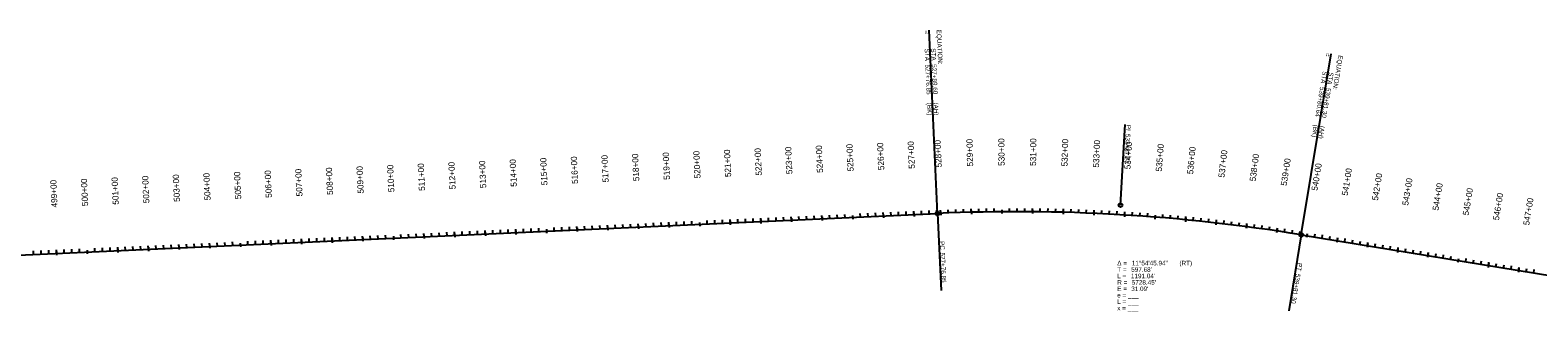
# Model space of a CAD drawing. Extents: x 22693007 to 22771804, y 6223023 to 6251673.
# Drawn here: x 22727487 to 22732405, y 6235764 to 6236738 of the extents above; entities that cross this region are included whole.
import ezdxf

# ---------------------------------------------------------------- set-up
doc = ezdxf.new("R2010")
doc.units = 0
for name, color, linetype in [('Default', 7, 'Continuous'), ('Draft_2', 7, 'Continuous'), ('NamedBoundary', 7, 'Continuous'), ('SheetBorder', 7, 'Continuous'), ('TextAlignment', 7, 'Continuous')]:
    doc.layers.add(name, color=color, linetype=linetype)

msp = doc.modelspace()

# ---------------------------------------------------------------- linework, layer by layer
at = {"layer": 'Default'}
for p, q in [((22723196, 6235810.3), (22730446.9, 6236138.4)), ((22731633.7, 6236068.7), (22733486.8, 6235764.5))]:
    msp.add_line(p, q, dxfattribs=at)
msp.add_arc((22730705.8, 6230415.9), 5728.5, 80.6784, 92.5911, dxfattribs=at)
at = {"layer": 'Draft_2'}
for p, q in [((22729870.6, 6236112.4), (22729870.1, 6236123.3)), ((22729970.5, 6236116.9), (22729970, 6236127.8)), ((22730070.4, 6236121.4), (22730069.9, 6236132.3)), ((22730170, 6236132), (22730170.6, 6236119.8)), ((22730270.2, 6236130.5), (22730269.7, 6236141.4)), ((22730370.1, 6236135), (22730369.6, 6236145.9)), ((22730457.3, 6236138.9), (22730456.8, 6236149.8)), ((22730557.2, 6236142.4), (22730556.9, 6236153.3)), ((22730657.1, 6236150.2), (22730657.2, 6236138)), ((22730757.2, 6236144.1), (22730757.3, 6236155)), ((22730857.2, 6236142.3), (22730857.5, 6236153.2)), ((22730957.1, 6236138.8), (22730957.6, 6236149.7)), ((22731057, 6236133.5), (22731057.6, 6236144.4)), ((22731157.2, 6236132.6), (22731156.2, 6236120.4)), ((22731256.3, 6236117.8), (22731257.4, 6236128.7)), ((22728771.7, 6236062.6), (22728771.2, 6236073.6)), ((22728871.6, 6236067.2), (22728871.1, 6236078.1)), ((22728971.5, 6236071.7), (22728971, 6236082.6)), ((22729071.4, 6236076.2), (22729070.9, 6236087.1)), ((22729171, 6236086.8), (22729171.6, 6236074.6)), ((22729271.2, 6236085.2), (22729270.7, 6236096.2)), ((22729371.1, 6236089.8), (22729370.6, 6236100.7)), ((22729471, 6236094.3), (22729470.5, 6236105.2)), ((22729570.9, 6236098.8), (22729570.4, 6236109.7)), ((22729670.5, 6236109.4), (22729671.1, 6236097.2)), ((22729770.7, 6236107.9), (22729770.2, 6236118.8)), ((22731355.8, 6236107.3), (22731357, 6236118.2)), ((22731455, 6236095.1), (22731456.5, 6236105.9)), ((22731554, 6236081.2), (22731555.7, 6236092)), ((22731653.2, 6236071.7), (22731651.2, 6236059.6)), ((22727772.8, 6236017.4), (22727772.3, 6236028.3)), ((22727872.7, 6236022), (22727872.2, 6236032.9)), ((22727972.6, 6236026.5), (22727972.1, 6236037.4)), ((22728072.4, 6236031), (22728072, 6236041.9)), ((22728172.1, 6236041.6), (22728172.6, 6236029.4)), ((22728272.2, 6236040), (22728271.7, 6236050.9)), ((22728372.1, 6236044.6), (22728371.6, 6236055.5)), ((22728472, 6236049.1), (22728471.5, 6236060)), ((22728571.9, 6236053.6), (22728571.4, 6236064.5)), ((22728671.6, 6236064.2), (22728672.1, 6236052)), ((22731750.8, 6236049.4), (22731752.6, 6236060.2)), ((22731849.5, 6236033.2), (22731851.3, 6236044)), ((22731948.2, 6236017), (22731950, 6236027.8)), ((22727573, 6236008.4), (22727572.5, 6236019.3)), ((22727672.6, 6236019), (22727673.1, 6236006.8)), ((22732046.9, 6236000.8), (22732048.7, 6236011.6)), ((22732146.6, 6235990.7), (22732144.6, 6235978.6)), ((22732244.2, 6235968.4), (22732246, 6235979.2)), ((22732342.9, 6235952.2), (22732344.7, 6235963))]:
    msp.add_line(p, q, dxfattribs=at)
at = {"layer": 'NamedBoundary'}
for p, q in [((22723196, 6235810.3), (22730446.9, 6236138.4)), ((22731633.7, 6236068.7), (22733486.8, 6235764.5))]:
    msp.add_line(p, q, dxfattribs=at)
msp.add_arc((22730705.8, 6230415.9), 5728.5, 80.6784, 92.5911, dxfattribs=at)
at = {"layer": 'SheetBorder'}
for p, q in [((22729795.7, 6236109), (22729795.2, 6236119.9)), ((22729820.7, 6236110.1), (22729820.2, 6236121)), ((22729845.6, 6236111.2), (22729845.1, 6236122.1)), ((22729895.6, 6236113.5), (22729895.1, 6236124.4)), ((22729920.6, 6236114.6), (22729920.1, 6236125.5)), ((22729945.5, 6236115.8), (22729945, 6236126.7)), ((22729970.2, 6236123), (22729970.8, 6236110.8)), ((22729995.5, 6236118), (22729995, 6236128.9)), ((22730020.5, 6236119.2), (22730020, 6236130.1)), ((22730045.4, 6236120.3), (22730044.9, 6236131.2)), ((22730070.1, 6236127.5), (22730070.7, 6236115.3)), ((22730095.4, 6236122.5), (22730094.9, 6236133.5)), ((22730120.4, 6236123.7), (22730119.9, 6236134.6)), ((22730145.3, 6236124.8), (22730144.8, 6236135.7)), ((22730170, 6236132), (22730170.6, 6236119.8)), ((22730195.3, 6236127.1), (22730194.8, 6236138)), ((22730220.2, 6236128.2), (22730219.8, 6236139.1)), ((22730245.2, 6236129.3), (22730244.7, 6236140.2)), ((22730269.9, 6236136.6), (22730270.5, 6236124.3)), ((22730295.2, 6236131.6), (22730294.7, 6236142.5)), ((22730320.1, 6236132.7), (22730319.7, 6236143.6)), ((22730345.1, 6236133.8), (22730344.6, 6236144.8)), ((22730369.8, 6236141.1), (22730370.4, 6236128.9)), ((22730395.1, 6236136.1), (22730394.6, 6236147)), ((22730420, 6236137.2), (22730419.6, 6236148.1)), ((22730445, 6236138.4), (22730444.5, 6236149.3)), ((22730457, 6236145), (22730457.5, 6236132.8)), ((22730482.2, 6236139.9), (22730481.8, 6236150.9)), ((22730507.2, 6236140.9), (22730506.8, 6236151.8)), ((22730532.2, 6236141.7), (22730531.9, 6236152.6)), ((22730557, 6236148.5), (22730557.4, 6236136.3)), ((22730582.2, 6236143), (22730582, 6236153.9)), ((22730607.2, 6236143.5), (22730607, 6236154.4)), ((22730632.2, 6236143.8), (22730632, 6236154.8)), ((22730657.1, 6236150.2), (22730657.2, 6236138)), ((22730682.2, 6236144.3), (22730682.1, 6236155.2)), ((22730707.2, 6236144.3), (22730707.2, 6236155.2)), ((22730732.2, 6236144.2), (22730732.2, 6236155.2)), ((22730757.2, 6236150.2), (22730757.1, 6236138)), ((22730782.2, 6236143.8), (22730782.3, 6236154.7)), ((22730807.2, 6236143.4), (22730807.4, 6236154.3)), ((22730832.2, 6236142.9), (22730832.4, 6236153.8)), ((22730857.3, 6236148.4), (22730857, 6236136.2)), ((22730882.2, 6236141.6), (22730882.5, 6236152.5)), ((22730907.1, 6236140.8), (22730907.5, 6236151.7)), ((22730932.1, 6236139.8), (22730932.6, 6236150.7)), ((22730957.4, 6236144.9), (22730956.8, 6236132.7)), ((22730982.1, 6236137.6), (22730982.6, 6236148.5)), ((22731007, 6236136.4), (22731007.6, 6236147.3)), ((22731032, 6236135), (22731032.6, 6236145.9)), ((22731057.3, 6236139.6), (22731056.6, 6236127.4)), ((22731081.9, 6236131.9), (22731082.6, 6236142.8)), ((22731106.9, 6236130.3), (22731107.6, 6236141.1)), ((22731131.8, 6236128.4), (22731132.6, 6236139.3)), ((22731157.2, 6236132.6), (22731156.2, 6236120.4)), ((22731181.6, 6236124.5), (22731182.5, 6236135.4)), ((22731206.5, 6236122.4), (22731207.5, 6236133.3)), ((22731231.4, 6236120.1), (22731232.4, 6236131)), ((22731256.9, 6236123.9), (22731255.7, 6236111.7)), ((22731281.2, 6236115.3), (22731282.3, 6236126.2)), ((22731306.1, 6236112.8), (22731307.2, 6236123.6)), ((22731330.9, 6236110.1), (22731332.1, 6236121)), ((22728696.8, 6236059.3), (22728696.3, 6236070.2)), ((22728721.8, 6236060.4), (22728721.3, 6236071.3)), ((22728746.8, 6236061.5), (22728746.3, 6236072.4)), ((22728796.7, 6236063.8), (22728796.2, 6236074.7)), ((22728821.7, 6236064.9), (22728821.2, 6236075.8)), ((22728846.7, 6236066), (22728846.2, 6236076.9)), ((22728871.4, 6236073.3), (22728871.9, 6236061)), ((22728896.6, 6236068.3), (22728896.1, 6236079.2)), ((22728921.6, 6236069.4), (22728921.1, 6236080.3)), ((22728946.6, 6236070.6), (22728946.1, 6236081.5)), ((22728971.3, 6236077.8), (22728971.8, 6236065.6)), ((22728996.5, 6236072.8), (22728996, 6236083.7)), ((22729021.5, 6236073.9), (22729021, 6236084.9)), ((22729046.5, 6236075.1), (22729046, 6236086)), ((22729071.1, 6236082.3), (22729071.7, 6236070.1)), ((22729096.4, 6236077.3), (22729095.9, 6236088.2)), ((22729121.4, 6236078.5), (22729120.9, 6236089.4)), ((22729146.3, 6236079.6), (22729145.9, 6236090.5)), ((22729171, 6236086.8), (22729171.6, 6236074.6)), ((22729196.3, 6236081.9), (22729195.8, 6236092.8)), ((22729221.3, 6236083), (22729220.8, 6236093.9)), ((22729246.2, 6236084.1), (22729245.8, 6236095)), ((22729270.9, 6236091.4), (22729271.5, 6236079.1)), ((22729296.2, 6236086.4), (22729295.7, 6236097.3)), ((22729321.2, 6236087.5), (22729320.7, 6236098.4)), ((22729346.1, 6236088.6), (22729345.7, 6236099.5)), ((22729370.8, 6236095.9), (22729371.4, 6236083.7)), ((22729396.1, 6236090.9), (22729395.6, 6236101.8)), ((22729421.1, 6236092), (22729420.6, 6236102.9)), ((22729446, 6236093.2), (22729445.5, 6236104.1)), ((22729470.7, 6236100.4), (22729471.3, 6236088.2)), ((22729496, 6236095.4), (22729495.5, 6236106.3)), ((22729521, 6236096.5), (22729520.5, 6236107.5)), ((22729545.9, 6236097.7), (22729545.4, 6236108.6)), ((22729570.6, 6236104.9), (22729571.2, 6236092.7)), ((22729595.9, 6236099.9), (22729595.4, 6236110.8)), ((22729620.9, 6236101.1), (22729620.4, 6236112)), ((22729645.8, 6236102.2), (22729645.3, 6236113.1)), ((22729670.5, 6236109.4), (22729671.1, 6236097.2)), ((22729695.8, 6236104.5), (22729695.3, 6236115.4)), ((22729720.8, 6236105.6), (22729720.3, 6236116.5)), ((22729745.7, 6236106.7), (22729745.2, 6236117.6)), ((22729770.4, 6236114), (22729771, 6236101.7)), ((22729870.3, 6236118.5), (22729870.9, 6236106.3)), ((22731356.5, 6236113.4), (22731355.1, 6236101.2)), ((22731380.6, 6236104.4), (22731381.9, 6236115.3)), ((22731405.4, 6236101.4), (22731406.8, 6236112.3)), ((22731430.2, 6236098.3), (22731431.6, 6236109.2)), ((22731455.8, 6236101.2), (22731454.2, 6236089)), ((22731479.8, 6236091.8), (22731481.3, 6236102.6)), ((22731504.6, 6236088.3), (22731506.1, 6236099.2)), ((22731529.3, 6236084.8), (22731530.9, 6236095.6)), ((22731555, 6236087.2), (22731553.1, 6236075.1)), ((22731578.8, 6236077.4), (22731580.4, 6236088.2)), ((22731603.5, 6236073.5), (22731605.2, 6236084.3)), ((22731628.1, 6236069.6), (22731629.9, 6236080.3)), ((22731653.2, 6236071.7), (22731651.2, 6236059.6)), ((22731676.8, 6236061.6), (22731678.6, 6236072.4)), ((22727622.9, 6236010.7), (22727622.4, 6236021.6)), ((22727647.9, 6236011.8), (22727647.4, 6236022.7)), ((22727697.8, 6236014), (22727697.3, 6236025)), ((22727722.8, 6236015.2), (22727722.3, 6236026.1)), ((22727747.8, 6236016.3), (22727747.3, 6236027.2)), ((22727772.5, 6236023.5), (22727773, 6236011.3)), ((22727797.7, 6236018.6), (22727797.2, 6236029.5)), ((22727822.7, 6236019.7), (22727822.2, 6236030.6)), ((22727847.7, 6236020.8), (22727847.2, 6236031.7)), ((22727872.4, 6236028.1), (22727872.9, 6236015.8)), ((22727897.6, 6236023.1), (22727897.1, 6236034)), ((22727922.6, 6236024.2), (22727922.1, 6236035.1)), ((22727947.6, 6236025.3), (22727947.1, 6236036.3)), ((22727972.3, 6236032.6), (22727972.8, 6236020.4)), ((22727997.5, 6236027.6), (22727997, 6236038.5)), ((22728022.5, 6236028.7), (22728022, 6236039.6)), ((22728047.5, 6236029.9), (22728047, 6236040.8)), ((22728072.2, 6236037.1), (22728072.7, 6236024.9)), ((22728097.4, 6236032.1), (22728096.9, 6236043)), ((22728122.4, 6236033.3), (22728121.9, 6236044.2)), ((22728147.4, 6236034.4), (22728146.9, 6236045.3)), ((22728172.1, 6236041.6), (22728172.6, 6236029.4)), ((22728197.3, 6236036.6), (22728196.8, 6236047.6)), ((22728222.3, 6236037.8), (22728221.8, 6236048.7)), ((22728247.3, 6236038.9), (22728246.8, 6236049.8)), ((22728272, 6236046.2), (22728272.5, 6236033.9)), ((22728297.2, 6236041.2), (22728296.7, 6236052.1)), ((22728322.2, 6236042.3), (22728321.7, 6236053.2)), ((22728347.2, 6236043.4), (22728346.7, 6236054.3)), ((22728371.9, 6236050.7), (22728372.4, 6236038.4)), ((22728397.1, 6236045.7), (22728396.6, 6236056.6)), ((22728422.1, 6236046.8), (22728421.6, 6236057.7)), ((22728447.1, 6236047.9), (22728446.6, 6236058.9)), ((22728471.8, 6236055.2), (22728472.3, 6236043)), ((22728497, 6236050.2), (22728496.5, 6236061.1)), ((22728522, 6236051.3), (22728521.5, 6236062.2)), ((22728547, 6236052.5), (22728546.5, 6236063.4)), ((22728571.7, 6236059.7), (22728572.2, 6236047.5)), ((22728596.9, 6236054.7), (22728596.4, 6236065.6)), ((22728621.9, 6236055.9), (22728621.4, 6236066.8)), ((22728646.9, 6236057), (22728646.4, 6236067.9)), ((22728671.6, 6236064.2), (22728672.1, 6236052)), ((22728771.5, 6236068.8), (22728772, 6236056.5)), ((22731701.5, 6236057.5), (22731703.3, 6236068.3)), ((22731726.2, 6236053.5), (22731727.9, 6236064.3)), ((22731751.8, 6236055.5), (22731749.9, 6236043.4)), ((22731775.5, 6236045.4), (22731777.3, 6236056.2)), ((22731800.2, 6236041.3), (22731802, 6236052.1)), ((22731824.9, 6236037.3), (22731826.6, 6236048.1)), ((22731850.5, 6236039.3), (22731848.5, 6236027.2)), ((22731874.2, 6236029.2), (22731876, 6236040)), ((22731898.9, 6236025.1), (22731900.6, 6236035.9)), ((22731923.5, 6236021.1), (22731925.3, 6236031.9)), ((22731949.2, 6236023.1), (22731947.2, 6236011)), ((22731972.9, 6236013), (22731974.6, 6236023.8)), ((22727498, 6236005), (22727497.5, 6236015.9)), ((22727523, 6236006.1), (22727522.5, 6236017)), ((22727548, 6236007.3), (22727547.5, 6236018.2)), ((22727572.7, 6236014.5), (22727573.2, 6236002.3)), ((22727597.9, 6236009.5), (22727597.4, 6236020.4)), ((22727672.6, 6236019), (22727673.1, 6236006.8)), ((22731997.5, 6236008.9), (22731999.3, 6236019.7)), ((22732022.2, 6236004.9), (22732024, 6236015.7)), ((22732047.9, 6236006.9), (22732045.9, 6235994.8)), ((22732071.6, 6235996.8), (22732073.3, 6236007.6)), ((22732096.2, 6235992.7), (22732098, 6236003.5)), ((22732120.9, 6235988.7), (22732122.7, 6235999.5)), ((22732146.6, 6235990.7), (22732144.6, 6235978.6)), ((22732170.2, 6235980.6), (22732172, 6235991.4)), ((22732194.9, 6235976.5), (22732196.7, 6235987.3)), ((22732219.6, 6235972.5), (22732221.3, 6235983.3)), ((22732245.2, 6235974.5), (22732243.2, 6235962.4)), ((22732268.9, 6235964.4), (22732270.7, 6235975.2)), ((22732293.6, 6235960.3), (22732295.3, 6235971.1)), ((22732318.3, 6235956.3), (22732320, 6235967.1)), ((22732343.9, 6235958.3), (22732341.9, 6235946.2)), ((22732367.6, 6235948.2), (22732369.4, 6235959)), ((22732392.3, 6235944.1), (22732394, 6235954.9))]:
    msp.add_line(p, q, dxfattribs=at)
at = {"layer": 'TextAlignment'}
for p, q in [((22730446.9, 6236138.4), (22730419.7, 6236737.8)), ((22730419.7, 6236737.8), (22730419.7, 6236737.8)), ((22731633.7, 6236068.7), (22731730.9, 6236660.7)), ((22731730.9, 6236660.7), (22731730.9, 6236660.7)), ((22731043.9, 6236165.5), (22731059.4, 6236429)), ((22731059.4, 6236429), (22731059.4, 6236429)), ((22730446.9, 6236138.4), (22730458.3, 6235886.7)), ((22731633.7, 6236068.7), (22731592.9, 6235820)), ((22730458.3, 6235886.7), (22730458.3, 6235886.7)), ((22731592.9, 6235820), (22731592.9, 6235820))]:
    msp.add_line(p, q, dxfattribs=at)
for centre, radius in [((22731043.9, 6236165.5), 6.24), ((22730446.9, 6236138.4), 6.24), ((22730446.9, 6236138.4), 5.34), ((22731633.7, 6236068.7), 6.24), ((22731633.7, 6236068.7), 5.34)]:
    msp.add_circle(centre, radius, dxfattribs=at)

# ---------------------------------------------------------------- texts
at = {"layer": 'Draft_2'}
for s, rotation, p in [('530+00', 90.4867, (22730665.9, 6236294.2)), ('535+00', 85.4857, (22731178.5, 6236275.3)), ('515+00', 92.5911, (22729174.6, 6236231)), ('520+00', 92.5911, (22729674, 6236253.6)), ('525+00', 92.5911, (22730173.5, 6236276.2)), ('505+00', 92.5911, (22728175.6, 6236185.8)), ('510+00', 92.5911, (22728675.1, 6236208.4)), ('540+00', 80.6784, (22731686.3, 6236212)), ('500+00', 92.5911, (22727676.1, 6236163.2)), ('545+00', 80.6784, (22732179.7, 6236131))]:
    msp.add_text(s, height=20.04, rotation=rotation, dxfattribs=at).set_placement(p)
at = {"layer": 'SheetBorder'}
for s, rotation, p in [('526+00', 92.5911, (22730273.4, 6236280.8)), ('527+00', 92.5911, (22730373.3, 6236285.3)), ('528+00', 92.4871, (22730460.8, 6236289.2)), ('529+00', 91.4869, (22730563.3, 6236292.6)), ('530+00', 90.4867, (22730665.9, 6236294.2)), ('531+00', 89.4865, (22730768.5, 6236294)), ('532+00', 88.4863, (22730871.1, 6236292)), ('533+00', 87.4861, (22730973.7, 6236288.2)), ('534+00', 86.4859, (22731076.2, 6236282.6)), ('535+00', 85.4857, (22731178.5, 6236275.3)), ('515+00', 92.5911, (22729174.6, 6236231)), ('516+00', 92.5911, (22729274.4, 6236235.5)), ('517+00', 92.5911, (22729374.3, 6236240.1)), ('518+00', 92.5911, (22729474.2, 6236244.6)), ('519+00', 92.5911, (22729574.1, 6236249.1)), ('520+00', 92.5911, (22729674, 6236253.6)), ('521+00', 92.5911, (22729773.9, 6236258.1)), ('522+00', 92.5911, (22729873.8, 6236262.7)), ('523+00', 92.5911, (22729973.7, 6236267.2)), ('524+00', 92.5911, (22730073.6, 6236271.7)), ('525+00', 92.5911, (22730173.5, 6236276.2)), ('536+00', 84.4855, (22731280.7, 6236266.1)), ('537+00', 83.4853, (22731382.8, 6236255.2)), ('538+00', 82.4851, (22731484.6, 6236242.5)), ('539+00', 81.4849, (22731586.2, 6236228)), ('504+00', 92.5911, (22728075.7, 6236181.3)), ('505+00', 92.5911, (22728175.6, 6236185.8)), ('506+00', 92.5911, (22728275.5, 6236190.3)), ('507+00', 92.5911, (22728375.4, 6236194.9)), ('508+00', 92.5911, (22728475.3, 6236199.4)), ('509+00', 92.5911, (22728575.2, 6236203.9)), ('510+00', 92.5911, (22728675.1, 6236208.4)), ('511+00', 92.5911, (22728775, 6236212.9)), ('512+00', 92.5911, (22728874.9, 6236217.5)), ('513+00', 92.5911, (22728974.8, 6236222)), ('514+00', 92.5911, (22729074.7, 6236226.5)), ('540+00', 80.6784, (22731686.3, 6236212)), ('541+00', 80.6784, (22731785, 6236195.8)), ('542+00', 80.6784, (22731883.7, 6236179.6)), ('499+00', 92.5911, (22727576.2, 6236158.7)), ('500+00', 92.5911, (22727676.1, 6236163.2)), ('501+00', 92.5911, (22727776, 6236167.7)), ('502+00', 92.5911, (22727875.9, 6236172.3)), ('503+00', 92.5911, (22727975.8, 6236176.8)), ('543+00', 80.6784, (22731982.4, 6236163.4)), ('544+00', 80.6784, (22732081.1, 6236147.2)), ('545+00', 80.6784, (22732179.7, 6236131)), ('546+00', 80.6784, (22732278.4, 6236114.8)), ('547+00', 80.6784, (22732377.1, 6236098.6))]:
    msp.add_text(s, height=20.04, rotation=rotation, dxfattribs=at).set_placement(p)
at = {"layer": 'TextAlignment'}
for s, rotation, p in [('=', 272.5911, (22730402.1, 6236737)), ('EQUATION:', 272.5911, (22730444, 6236738.9)), ('STA ', 272.5911, (22730404.8, 6236677.1)), ('STA ', 272.5911, (22730425.8, 6236678)), ('=', 260.6784, (22731713.4, 6236663.6)), ('527+76.85', 272.5911, (22730407.1, 6236625.2)), ('527+89.60', 272.5911, (22730428.1, 6236626.2)), ('EQUATION:', 260.6784, (22731754.9, 6236656.8)), ('STA ', 260.6784, (22731703.7, 6236604.4)), ('STA ', 260.6784, (22731724.4, 6236601)), ('539+80.64', 260.6784, (22731695.3, 6236553.1)), ('539+81.30', 260.6784, (22731716, 6236549.7)), ('(BK)', 272.5911, (22730412.8, 6236500)), ('(AH)', 272.5911, (22730433.8, 6236501)), ('PI ', 266.6347, (22731062.7, 6236428.8)), ('(BK)', 260.6784, (22731675, 6236429.5)), ('(AH)', 260.6784, (22731695.7, 6236426.1)), ('533+87.27', 266.6347, (22731061, 6236399)), ('PC', 272.5911, (22730454.3, 6236047.9)), ('527+76.85', 272.5911, (22730455.9, 6236010.6)), ('PT', 260.6784, (22731622.2, 6235977.9)), ('539+81.30', 260.6784, (22731616.3, 6235942.1))]:
    msp.add_text(s, height=15, rotation=rotation, dxfattribs=at).set_placement(p)
for s, p in [('Δ = ', (22731033.2, 6235968.8)), ('11°54\'45.94"', (22731080.7, 6235968.8)), (' (RT)', (22731230.4, 6235968.8)), ('T = ', (22731033.2, 6235947.8)), ('L = ', (22731033.2, 6235926.8)), ("1191.04'", (22731077.9, 6235926.8)), ("597.68'", (22731078.9, 6235947.8)), ('e = ___ ', (22731033.2, 6235863.8)), ('R = ', (22731033.2, 6235905.8)), ('E = ', (22731033.2, 6235884.8)), ("31.09'", (22731078.9, 6235884.8)), ("5728.45'", (22731080.7, 6235905.8)), ('x = ___', (22731033.2, 6235821.8)), ('L = ___', (22731033.2, 6235842.8))]:
    msp.add_text(s, height=15, dxfattribs=at).set_placement(p)

doc.saveas('drawing.dxf')
